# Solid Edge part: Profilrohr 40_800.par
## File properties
Username: ahadarics
Dokumentum tartalom típus: 0
Author: ahadarics
Last saved by: ahadarics
Revision: 96
Sűrűség: 0,000 kg/m^3
Pontosság: 0,990
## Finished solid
Body 1: solid body, 175 faces, 519 edges, 346 vertices.
  Faces by surface: cylinder 107, plane 68
  Edges by curve: line 305, circle 214
Bounding box of the edges (mm): 51.354 x 51.354 x 843.000, from (-25.6768, -25.6768, -809) to (25.6768, 25.6768, 34).
Cylindrical faces by radius (mm): R0.1 x16, R0.2 x30, R0.5 x28, R1 x8, R2.7 x8, R3.5 x4, R5 x4, R20 x1, R22 x8
Planar faces by outward normal: +x 6, +y 6, +z 1, -x 4, -y 4, -z 1, oblique 46
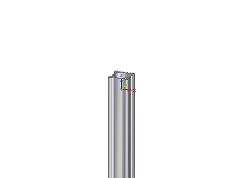
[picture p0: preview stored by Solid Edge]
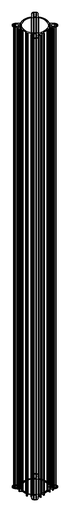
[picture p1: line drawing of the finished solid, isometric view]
